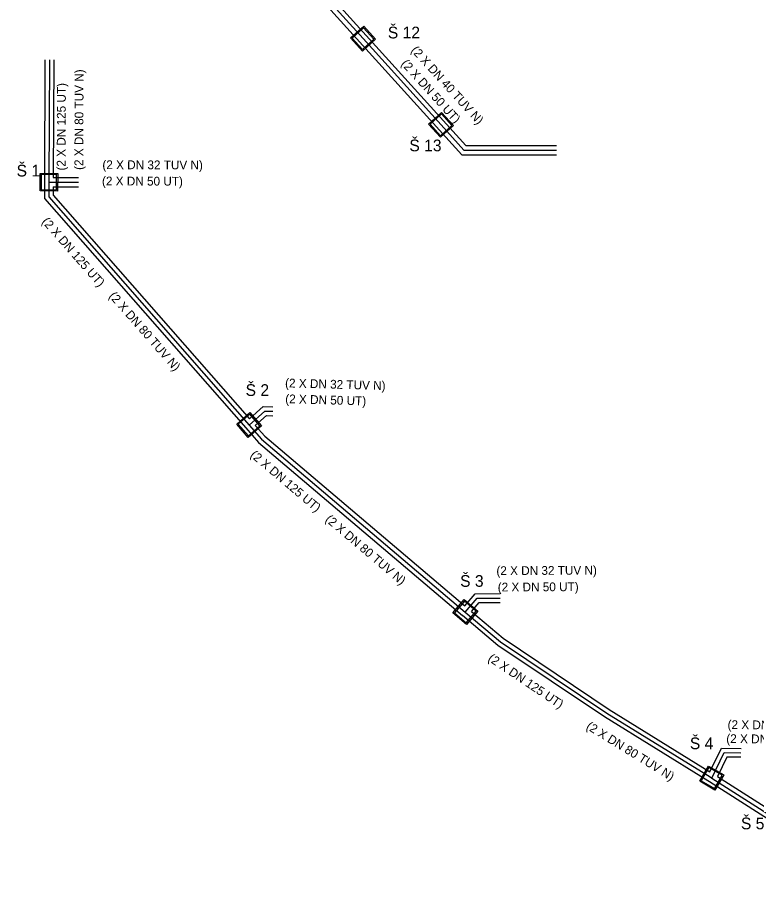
# Model space of a CAD drawing. Extents: x -606118 to -604472, y -1157869 to -1156854.
# Drawn here: x -605302.7 to -605176.4, y -1157859 to -1157710.9 of the extents above; entities that cross this region are included whole.
import ezdxf

# ---------------------------------------------------------------- set-up
doc = ezdxf.new("R2010")
doc.units = 0
for name, color, linetype in [('Osa trasy teplovodu', 7, 'Continuous'), ('označení šachty', 7, 'Continuous'), ('Teplovod - trasa - okraj', 7, 'Continuous'), ('Teplovod - trasa popis', 7, 'Continuous'), ('Teplovod - trasa popis 2', 7, 'Continuous'), ('Šachta trasy teplovodu', 7, 'Continuous')]:
    doc.layers.add(name, color=color, linetype=linetype)

msp = doc.modelspace()

# ---------------------------------------------------------------- linework, layer by layer
at = {"layer": 'Osa trasy teplovodu'}
for p, q in [((-605297.24, -1157718.18), (-605297.32, -1157739.08)), ((-605297.32, -1157739.08), (-605292.28, -1157739.09))]:
    msp.add_line(p, q, dxfattribs=at)
for points in [[(-605258.69, -1157692.12), (-605258.7, -1157697.93), (-605243.66, -1157714.56), (-605230.34, -1157729.29), (-605226.44, -1157733.6), (-605210.63, -1157733.61)], [(-605297.32, -1157739.08), (-605297.33, -1157741.55), (-605263.12, -1157780.52)], [(-605263.12, -1157780.52), (-605260.41, -1157778.14), (-605259.07, -1157778.18)], [(-605263.12, -1157780.52), (-605260.98, -1157782.96), (-605226.19, -1157812.44)], [(-605226.19, -1157812.44), (-605224.18, -1157810.07), (-605220.22, -1157810.05)], [(-605226.19, -1157812.44), (-605220.18, -1157817.53), (-605202.03, -1157829.73), (-605184.38, -1157840.6), (-605184.1, -1157840.78)], [(-605184.1, -1157840.78), (-605181.97, -1157836.45), (-605179.11, -1157836.47)], [(-605184.1, -1157840.78), (-605172.81, -1157847.96), (-605172.81, -1157847.96), (-605141.95, -1157858.01), (-605137.17, -1157858.23)]]:
    msp.add_lwpolyline(points, dxfattribs=at)
at = {"layer": 'Teplovod - trasa - okraj'}
for p, q in [((-605297.99, -1157718.18), (-605298.07, -1157739.07)), ((-605296.49, -1157718.19), (-605296.57, -1157738.28)), ((-605296.57, -1157738.28), (-605292.28, -1157738.29)), ((-605296.57, -1157739.88), (-605292.28, -1157739.89))]:
    msp.add_line(p, q, dxfattribs=at)
for points in [[(-605257.89, -1157692.92), (-605257.9, -1157697.62), (-605226.08, -1157732.8), (-605210.62, -1157732.81)], [(-605259.49, -1157693.12), (-605259.5, -1157698.24), (-605226.8, -1157734.4), (-605210.63, -1157734.41)], [(-605298.07, -1157739.07), (-605298.08, -1157741.83), (-605263.69, -1157781.02)], [(-605296.57, -1157739.88), (-605296.58, -1157741.27), (-605263.05, -1157779.46)], [(-605263.05, -1157779.46), (-605260.69, -1157777.39), (-605259.05, -1157777.43)], [(-605262.06, -1157780.59), (-605260.14, -1157778.9), (-605259.09, -1157778.93)], [(-605263.69, -1157781.02), (-605261.5, -1157783.5), (-605226.67, -1157813.01)], [(-605262.06, -1157780.59), (-605260.45, -1157782.43), (-605226.27, -1157811.39)], [(-605226.27, -1157811.39), (-605224.53, -1157809.32), (-605220.23, -1157809.3)], [(-605225.13, -1157812.35), (-605223.83, -1157810.82), (-605220.22, -1157810.8)], [(-605225.13, -1157812.35), (-605219.73, -1157816.93), (-605201.62, -1157829.1), (-605184.41, -1157839.71)], [(-605184.5, -1157841.41), (-605184.78, -1157841.24), (-605202.44, -1157830.36), (-605220.64, -1157818.13), (-605226.67, -1157813.01)], [(-605184.41, -1157839.71), (-605182.44, -1157835.69), (-605179.1, -1157835.72)], [(-605179.11, -1157837.22), (-605181.51, -1157837.2), (-605183.13, -1157840.51)], [(-605183.13, -1157840.51), (-605172.49, -1157847.27), (-605141.82, -1157857.27), (-605137.87, -1157857.45)], [(-605137.2, -1157858.98), (-605142.09, -1157858.76), (-605173.14, -1157848.64), (-605184.5, -1157841.41)]]:
    msp.add_lwpolyline(points, dxfattribs=at)
at = {"layer": 'Šachta trasy teplovodu'}
for points in [[(-605245.78, -1157714.45), (-605243.55, -1157712.44), (-605241.53, -1157714.66), (-605243.76, -1157716.68), (-605245.78, -1157714.45)], [(-605243.75, -1157716.42), (-605241.8, -1157714.65), (-605243.57, -1157712.7), (-605245.52, -1157714.47), (-605243.75, -1157716.42)], [(-605232.46, -1157729.18), (-605230.23, -1157727.16), (-605228.21, -1157729.39), (-605230.44, -1157731.41), (-605232.46, -1157729.18)], [(-605230.43, -1157731.14), (-605228.48, -1157729.38), (-605230.24, -1157727.43), (-605232.19, -1157729.19), (-605230.43, -1157731.14)], [(-605295.83, -1157740.58), (-605298.83, -1157740.57), (-605298.82, -1157737.57), (-605295.81, -1157737.58), (-605295.83, -1157740.58)], [(-605296, -1157737.77), (-605298.63, -1157737.76), (-605298.64, -1157740.39), (-605296.01, -1157740.4), (-605296, -1157737.77)], [(-605265.24, -1157780.38), (-605262.98, -1157778.4), (-605261, -1157780.66), (-605263.26, -1157782.64), (-605265.24, -1157780.38)], [(-605263.24, -1157782.37), (-605261.26, -1157780.64), (-605263, -1157778.66), (-605264.97, -1157780.4), (-605263.24, -1157782.37)], [(-605228.3, -1157812.61), (-605226.36, -1157810.32), (-605224.07, -1157812.27), (-605226.01, -1157814.56), (-605228.3, -1157812.61)], [(-605226.03, -1157814.29), (-605224.33, -1157812.29), (-605226.34, -1157810.59), (-605228.04, -1157812.59), (-605226.03, -1157814.29)], [(-605186.15, -1157841.33), (-605184.64, -1157838.73), (-605182.04, -1157840.23), (-605183.55, -1157842.83), (-605186.15, -1157841.33)], [(-605183.62, -1157842.58), (-605182.3, -1157840.3), (-605184.57, -1157838.98), (-605185.89, -1157841.26), (-605183.62, -1157842.58)]]:
    msp.add_lwpolyline(points, dxfattribs=at)

# ---------------------------------------------------------------- texts
at = {"layer": 'označení šachty'}
for s, p in [('Š 12', (-605239.43, -1157714.53)), ('Š 13', (-605235.75, -1157733.8)), ('Š 1', (-605302.83, -1157738.1)), ('Š 2', (-605263.72, -1157775.56)), ('Š 3', (-605227.08, -1157808.14)), ('Š 4', (-605187.84, -1157835.86)), ('Š 5', (-605179.12, -1157849.53))]:
    msp.add_text(s, height=2, dxfattribs=at).set_placement(p)
at = {"layer": 'Teplovod - trasa popis'}
for s, rotation, p in [('(2 X DN 50 UT)', 312.1474, (-605237.26, -1157718.93)), ('(2 X DN 125 UT)', 89.7825, (-605294.48, -1157737.08)), ('(2 X DN 50 UT)', 359.8175, (-605288.25, -1157739.62)), ('(2 X DN 125 UT)', 311.288, (-605298.61, -1157745.86)), ('(2 X DN 50 UT)', 358.3851, (-605256.96, -1157776.79)), ('(2 X DN 125 UT)', 319.7104, (-605263.05, -1157785.83)), ('(2 X DN 50 UT)', 0.2865, (-605220.65, -1157808.94)), ('(2 X DN 125 UT)', 326.0703, (-605222.45, -1157820.67)), ('(2 X DN 50 UT)', 359.4737, (-605181.62, -1157834.8))]:
    msp.add_text(s, height=1.5, rotation=rotation, dxfattribs=at).set_placement(p)
at = {"layer": 'Teplovod - trasa popis 2'}
for s, rotation, p in [('(2 X DN 40 TUV N)', 312.1474, (-605235.56, -1157716.63)), ('(2 X DN 80 TUV N)', 89.7825, (-605291.46, -1157736.98)), ('(2 X DN 32 TUV N)', 359.8175, (-605288.18, -1157736.84)), ('(2 X DN 80 TUV N)', 311.288, (-605287.16, -1157758.56)), ('(2 X DN 32 TUV N)', 358.3851, (-605256.99, -1157774.08)), ('(2 X DN 80 TUV N)', 319.7104, (-605250.24, -1157796.83)), ('(2 X DN 32 TUV N)', 0.2865, (-605220.88, -1157806.14)), ('(2 X DN 80 TUV N)', 328.3621, (-605205.68, -1157832.31)), ('(2 X DN 40 TUV N)', 359.4737, (-605181.4, -1157832.41))]:
    msp.add_text(s, height=1.5, rotation=rotation, dxfattribs=at).set_placement(p)

doc.saveas('drawing.dxf')
